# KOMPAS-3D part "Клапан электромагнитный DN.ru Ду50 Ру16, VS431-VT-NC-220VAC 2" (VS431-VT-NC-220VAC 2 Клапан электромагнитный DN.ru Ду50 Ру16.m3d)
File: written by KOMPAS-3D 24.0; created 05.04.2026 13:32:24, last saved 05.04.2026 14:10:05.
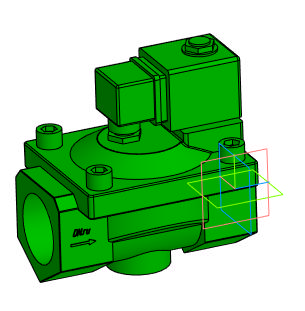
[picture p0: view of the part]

Document properties: Автор: artio; Полное имя файла: C:\Users\artio\OneDrive\Рабочий стол\Клапан электромагнитный DN.ru\VS431\VS431-VT-NC\VS431-VT-NC-220VAC\Ду50\VS431-VT-NC-220VAC 2 Клапан электромагнитный DN.ru Ду50 Ру16.m3d

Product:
- Body: Тело 1  | qty 1
    Масса: 6.703651
- Part/product: Клапан электромагнитный DN.ru Ду50 Ру16  | designation VS431-VT-NC-220VAC 2
    Масса: 3.341
    Раздел спецификации: Прочие изделия
    Примечание: D130-04717
    additional columns: ef56311e-7521-43dc-8291-0e6108b3d81d; artio; c; Шероховатость не задана; Да

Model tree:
1. Операция без истории:1

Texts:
  VS431-VT-NC-220VAC 2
